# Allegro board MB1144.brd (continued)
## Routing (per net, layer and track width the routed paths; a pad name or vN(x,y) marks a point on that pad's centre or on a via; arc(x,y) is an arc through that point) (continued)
LCDSEG3: length 39.4
  TOP w0.127: v1(86.2,113.67) 86.33,113.54 88.11,113.54 88.61,114.05 88.61,115.19 89.88,116.46 89.88,120.65 89.63,120.9 81.5,120.9 R68.1
  BOTTOM w0.127: CN11.41 83.82,95.92 85.06,97.16 85.06,101.09 86.84,102.87 86.84,112.9 86.2,113.54 v1(86.2,113.67)
LCDSEG4: length 52.8
  TOP w0.127: v1(93.44,96.9) 82.3,96.9 CN11.39 ; v1(89.68,114.83) 89.71,114.86 89.71,115.14 90.65,116.08 90.65,121.16 88.87,122.94 81.5,122.94 80.74,123.7 R66.1
  BOTTOM w0.127: v1(93.44,96.9) 93.95,97.41 93.95,110.36 92.81,111.51 92.81,113.16 92.04,113.92 92.04,115.19 91.79,115.44 90.29,115.44 v1(89.68,114.83)
LCDSEG5: length 56.7
  TOP w0.127: v1(92.81,97.41) 92.68,97.28 81.38,97.28 79.98,95.89 CN11.37 ; 80.36,127.51 81.12,127.51 81.5,127.89 84.42,127.89 85.06,127.25 88.87,127.25 92.68,123.44 92.68,114.81 91.92,114.05 v1(91.92,113.41)
  BOTTOM w0.127: v1(92.81,97.41) 92.96,97.41 93.69,98.15 93.69,110.11 92.55,111.25 92.55,113.03 92.17,113.41 v1(91.92,113.41)
LCDSEG6: length 65.9
  TOP w0.127: v1(88.87,135.38) 88.36,135.38 84.6,131.62 84.6,130.61 84.17,130.18 81.88,130.18 80.61,128.91 R56.1
  BOTTOM w0.127: v1(88.87,135.38) 94.15,135.38 94.84,134.7 98.7,134.7 99.92,133.48 99.92,111.63 96.74,108.46 96.67,108.46 96.03,107.82 96.03,98.81 93.11,95.89 CN11.47
LCDSEG7: length 193.2
  TOP w0.127: v1(72.36,48.9) 72.36,48.77 72.49,48.64 72.49,48.23 U24.6 ; v1(112.97,87.35) 112.74,87.12 RS1.9 ; v1(35.91,90.81) 36.8,91.69 48.86,91.69 49.5,92.33 54.71,92.33 55.59,93.22 60.29,93.22 v1(60.42,93.34) 60.8,93.73 64.36,93.73 65.3,94.67 67.61,94.67 67.79,94.49 69.82,94.49 70.07,94.23 86.07,94.23 87.73,95.89 CN11.45 89.02,95.89 90.19,94.72 94.53,94.72 94.89,95.07 107.99,95.07 v1(108.25,94.82) ; v1(43.28,112.14) 42.77,112.65 42.77,120.14 44.04,121.41 44.04,123.06 45.56,124.59 48.1,124.59 48.36,124.84 50.77,124.84 51.07,125.15 U7.133
  BOTTOM w0.127: v1(35.91,90.81) 35.91,92.08 34.44,93.55 34.44,104.55 42.03,112.14 v1(43.28,112.14) ; v1(72.36,48.9) 69.89,48.9 69.06,49.73 67.76,49.73 67.13,49.1 67.13,47.21 66.85,46.93 66.07,46.93 65.82,47.19 65.82,50.48 65.25,51.05 65.25,58.88 64.56,59.56 64.56,65.53 62.33,67.77 62.33,74.6 59.53,77.39 59.53,92.46 v1(60.42,93.34) ; v1(108.25,94.82) 108.93,94.13 108.93,90.88 112.5,87.31 112.93,87.31 v1(112.97,87.35)
LCDSEG8: length 243.3
  TOP w0.127: U23.19 65.62,47.85 65.97,48.19 v1(66.66,48.19) ; v1(35.91,87.5) 38.45,87.5 42.26,83.69 44.67,83.69 46.81,85.83 50.54,85.83 50.95,86.23 52.65,86.23 v1(53.18,86.77) ; v1(112.97,85.72) 112.92,85.72 112.57,86.08 112.02,86.08 112,86.11 RS1.5 ; v1(43.28,112.9) 43.02,113.16 43.02,119.89 44.29,121.16 44.29,122.81 45.69,124.21 48.1,124.21 48.36,124.46 50.9,124.46 51.08,124.65 U7.134 ; v1(53.31,92.84) 54.32,92.84 54.96,93.47 59.91,93.47 60.42,93.98 64.23,93.98 65.25,95 67.66,95 67.91,94.74 70.07,94.74 70.33,94.49 85.69,94.49 86.36,95.15 CN11.43 ; v1(102.69,89.08) 108.45,89.08 v1(108.71,88.82)
  BOTTOM w0.127: v1(102.69,89.08) 102.13,89.08 99.28,86.23 85.82,86.23 84.55,87.5 84.55,93.22 86.36,95.03 CN11.43 ; v1(53.31,92.84) 53.31,90.3 52.57,89.56 52.57,87.43 53.18,86.82 v1(53.18,86.77) ; v1(35.91,87.5) 35.4,88.01 35.4,92.2 34.18,93.42 34.18,104.67 42.41,112.9 v1(43.28,112.9) ; v1(108.71,88.82) 108.68,88.8 108.68,87.66 109.16,87.17 111.07,87.17 112.31,85.93 112.77,85.93 v1(112.97,85.72) 115.54,83.16 115.54,78.87 115.34,78.66 115.34,78.31 115.54,78.11 115.54,72.8 111.22,68.48 111.22,59.56 110.97,59.31 110.97,50.42 109.16,48.62 96.44,48.62 95.65,49.4 79.6,49.4 78.96,50.04 72.1,50.04 71.76,50.38 67.64,50.38 66.54,49.27 66.54,48.31 v1(66.66,48.19)
LCDSEG9: length 65.2
  TOP w0.127: v1(28.3,94.16) 28.37,94.23 46.61,94.23 CN11.13 ; v1(50.01,123.44) 50.26,123.44 50.96,124.15 U7.135
  BOTTOM w0.127: v1(50.01,123.44) 49.5,122.94 46.45,122.94 42.89,119.38 40.35,119.38 29.28,108.3 29.28,100.57 28.52,99.81 28.52,94.39 v1(28.3,94.16)
LCDSEG10: length 126.7
  TOP w0.127: R50.1 80.74,135.64 81.76,134.62 84.68,134.62 88.61,138.56 v1(88.87,138.56) ; v1(62.73,101.75) 62.73,101.7 61.69,100.66 58.39,100.66 57.58,101.47 48.84,101.47 46.68,99.31 46.68,96.85 45.72,95.89 CN11.11 ; v1(65.75,94.13) 65.91,93.98 86.46,93.98 86.71,94.23 93.72,94.23 v1(93.92,94.03)
  BOTTOM w0.127: v1(93.92,94.03) 96.69,96.8 96.69,107.26 100.43,111 100.43,134.9 98.04,137.29 94.08,137.29 92.17,139.19 89.5,139.19 v1(88.87,138.56) ; v1(65.75,94.13) 64.92,94.97 64.92,99.01 62.73,101.19 v1(62.73,101.75)
LCDSEG11: length 205.8
  TOP w0.127: v1(110.08,137.92) 109.76,138.24 109.38,138.24 109.32,138.3 104.24,138.3 102.71,139.83 101.31,139.83 100.93,140.21 88.49,140.21 84.68,136.4 81.76,136.4 80.99,137.16 R48.1 ; v1(47.21,62.99) 47.36,63.14 48.79,63.14 51.73,60.2 60.01,60.2 61.28,61.47 67.2,61.47 71.52,65.79 86.46,65.79 v1(87.34,64.9)
  BOTTOM w0.127: v1(47.21,62.99) 47.21,69.47 44.06,72.62 44.06,93.75 43.18,94.63 CN11.9 ; v1(87.34,64.9) 103.73,64.9 108.12,69.29 108.12,79.27 106.95,80.44 106.95,93.65 107.61,94.31 107.61,95.33 108.6,96.32 108.6,110.06 107.03,111.63 107.03,111.96 107.05,111.99 107.05,114.99 107.26,115.19 107.26,115.21 108.05,116 108.05,126.62 108.3,126.87 108.3,136.32 109.9,137.92 v1(110.08,137.92)
LCDSEG12: length 176.4
  TOP w0.127: R39.2 v1(71.85,145.67) ; v1(22.98,133.93) 22.98,134.04 23.97,135.03 23.97,137.67 25.88,139.57 v1(29.94,139.57) ; v1(52.14,71.53) 51.96,71.35 51.12,71.35 50.9,71.12 32.1,71.12 v1(31.77,70.79)
  BOTTOM w0.127: v1(52.14,71.53) 52.14,71.78 55.01,74.65 55.01,85.8 54.71,86.11 54.71,92.33 55.88,93.5 CN11.19 ; v1(31.77,70.79) 31.77,71.2 28.31,74.65 28.31,75.59 28.11,75.79 28.11,88.44 23.34,93.21 23.34,95.96 21.48,97.82 21.48,100.75 23.98,103.25 23.98,111.12 23.62,111.48 23.62,113.18 24.48,114.05 24.48,124.43 24.86,124.82 24.86,126.62 22.52,128.96 22.52,133.48 v1(22.98,133.93) ; v1(29.94,139.57) 50.51,139.57 52.29,141.35 55.9,141.35 57.8,139.45 60.17,139.45 62.45,141.73 70.2,141.73 71.85,143.38 v1(71.85,145.67)
LCDSEG13: length 158
  TOP w0.127: R38.1 v1(69.31,145.67) ; v1(52.29,86.74) 52.17,86.61 50.95,86.61 50.41,86.08 46.65,86.08 44.52,83.95 42.39,83.95 38.32,88.01 33.12,88.01 30.19,85.09 v1(22.32,85.09) ; v1(32.61,140.08) 25.37,140.08 23.46,138.18 23.46,135.08 22.37,133.99 22.37,116.51 21.18,115.32 21.18,111.38 v1(21.3,111.25)
  BOTTOM w0.127: v1(52.29,86.74) 52.29,87 52.19,87.1 52.19,89.81 52.8,90.42 52.8,93.09 53.34,93.63 CN11.17 ; v1(22.32,85.09) 21.56,85.85 21.56,88.17 17.57,92.15 17.57,102.23 16.48,103.33 16.48,104.78 17.57,105.87 17.57,107.67 21.15,111.25 v1(21.3,111.25) ; v1(69.31,145.67) 69.44,145.67 71.09,144.02 71.09,143 70.07,141.99 62.2,141.99 60.04,139.83 57.8,139.83 55.9,141.73 51.91,141.73 50.26,140.08 v1(32.61,140.08)
LCDSEG14: length 56.7
  TOP w0.127: v1(57.63,100.46) 57.07,99.9 57.07,97.66 56.74,97.33 55.21,97.33 54.78,96.9 51.82,96.9 CN11.15 ; v1(65.88,125.48) 65.88,129.16 71.25,134.53 U7.75
  BOTTOM w0.127: v1(65.88,125.48) 65.88,125.6 65.63,125.86 63.82,125.86 59.79,121.82 59.79,115.32 59.28,114.81 59.28,114.17 59.79,113.67 59.79,110.87 58.97,110.06 58.97,102.69 57.63,101.35 v1(57.63,100.46)
LCDSEG15: length 49.9
  TOP w0.127: U7.76 70.75,134.53 65.37,129.16 65.37,125.09 v1(65.88,124.59)
  BOTTOM w0.127: v1(65.88,124.59) 65.88,124.08 64.36,122.56 63.19,122.56 61.94,121.31 61.94,109.98 60.75,108.79 60.75,100.76 62.58,98.93 62.58,96.52 63.21,95.89 CN11.25
LCDSEG16: length 51.4
  TOP w0.127: v1(48.23,93.22) 48.61,93.6 51.28,93.6 52.04,94.36 53.82,94.36 54.2,94.74 59.07,94.74 60.22,95.89 CN11.23 ; U7.139 50.23,122.15 49.5,121.41 45.69,121.41 44.55,120.27 44.55,111.07 v1(44.44,110.97)
  BOTTOM w0.127: v1(48.23,93.22) 47.36,94.08 47.36,106.33 44.44,109.25 v1(44.44,110.97)
LCDSEG17: length 213.9
  TOP w0.127: U7.110 55.85,136.65 57.42,135.08 57.42,132.05 56.22,130.84 56.22,126.35 v1(56.16,126.3) ; v1(64.93,48.51) 64.93,48.45 64.48,48.01 64.48,47.5 64.62,47.36 U23.17 ; v1(31.69,92.86) 32.05,93.22 47.21,93.22 48.1,94.11 51.02,94.11 51.78,94.87 53.56,94.87 54.45,95.76 54.45,95.89 55.47,96.9 57.4,96.9 CN11.21 ; v1(107.79,93.85) 107.54,94.11 105.78,94.11 105.38,94.51 96.64,94.51 94.84,92.71 64.33,92.71 62.76,91.14 62.76,89.84 62.2,89.28 56.36,89.28 56.1,89.53 v1(56.1,89.66) ; v1(113.61,87.3) 113.61,87.33 112.9,86.61 112,86.61 RS1.7
  BOTTOM w0.127: v1(64.93,48.51) 64.81,48.63 64.81,58.72 63.6,59.94 63.6,65.66 61.97,67.28 61.97,72.11 57.37,76.71 57.37,85.34 56.86,85.85 56.86,88.9 v1(56.1,89.66) 56.1,91.19 57.5,92.58 57.5,94.96 CN11.21 ; v1(56.16,126.3) 56.16,125.85 54.85,124.54 54.85,124.41 51.72,121.27 50.48,121.27 50.02,120.81 47.06,120.81 43.85,117.6 41.09,117.6 40.68,117.19 40.68,117.09 31.2,107.62 31.2,99.8 30.73,99.33 30.73,94.22 31.69,93.25 v1(31.69,92.86) ; v1(107.79,93.85) 108.68,92.96 108.68,90.75 112.59,86.84 113.13,86.84 113.61,87.33 v1(113.61,87.3)
LCDSEG18: length 26.2
  TOP w0.127: v1(70.07,108.03) 70.07,108.33 70.71,108.97 R97.1
  BOTTOM w0.127: v1(70.07,108.03) 70.07,108.33 69.56,108.84 64.23,108.84 62.6,107.21 62.6,104.55 67.2,99.95 69.44,99.95 70.03,99.36 70.03,96.98 CN11.31
LCDSEG19: length 26.1
  TOP w0.127: v1(70.71,107.95) 71.22,107.95 R98.1
  BOTTOM w0.127: CN11.29 67.13,97.34 67.13,99.59 62.3,104.42 62.3,107.44 64.08,109.22 69.95,109.22 70.71,108.46 v1(70.71,107.95)
LCDSEG20: length 27.7
  TOP w0.127: R99.1 73.76,108.58 72.99,107.82 v1(71.85,107.82)
  BOTTOM w0.127: CN11.27 65.81,95.89 65.17,96.52 65.17,99.85 65.12,99.9 65.12,101.21 62.02,104.3 62.02,107.7 63.93,109.6 70.2,109.6 71.34,108.46 71.34,108.2 71.72,107.82 v1(71.85,107.82)
LCDSEG21: length 56.9
  TOP w0.127: U7.137 51.74,123.15 51.53,122.94 49.88,122.94 49.37,123.44 49.37,123.7 49.12,123.95 46.07,123.95 44.67,122.56 44.67,121.03 43.94,120.29 43.94,107.65 v1(44.06,107.52)
  BOTTOM w0.127: v1(44.06,107.52) 44.49,107.09 44.49,105.05 43.48,104.04 43.48,101.88 42.31,100.71 42.31,94.97 43.78,93.5 43.78,82.96 42.11,81.28 42.11,79.17 43.17,78.11 CN14.9
LCDSEG22: length 92.8
  TOP w0.127: v1(90.9,114.55) 90.9,115.19 91.66,115.95 91.66,120.52 91.64,120.55 91.64,121.79 88.46,124.97 84.13,124.97 83.81,125.28 ; CN14.11 46.07,78.11 47.24,79.27 49.07,79.27 49.68,79.88 49.68,81.38 50.77,82.47 50.77,84.84 51.4,85.47 61.56,85.47 62.4,84.63 70.1,84.63 70.96,85.5 83.05,85.5 83.76,86.21 83.76,89.56 85.52,91.31 v1(85.95,91.31)
  BOTTOM w0.127: v1(85.95,91.31) 85.95,91.72 87.98,93.75 87.98,101.3 89.78,103.1 89.78,103.78 89.81,103.81 89.81,113.59 90.77,114.55 v1(90.9,114.55)
LCDSEG23: length 97.7
  TOP w0.127: CN14.13 49.93,79.78 49.93,81.18 51.02,82.27 51.02,84.71 51.53,85.22 61.41,85.22 62.27,84.35 70.2,84.35 71.09,85.24 83.18,85.24 84.02,86.08 84.02,89.43 85.13,90.55 85.82,90.55 v1(86.71,91.44) ; 80.36,125.35 80.74,125.35 81.76,126.36 84.42,126.36 84.68,126.62 87.98,126.62 92.17,122.43 92.17,115.06 91.03,113.92 v1(90.9,113.92)
  BOTTOM w0.127: v1(90.9,113.92) 90.9,111.51 92.55,109.86 92.55,104.62 90.01,102.08 90.01,95.33 86.71,92.02 v1(86.71,91.44)
LCDSEG24: length 101.8
  TOP w0.127: v1(42.54,103.07) 42.44,103.07 42.06,103.45 42.06,105.74 40.61,107.19 40.61,109.09 40.86,109.35 40.86,117.86 37.56,121.16 37.56,128.91 45.31,136.65 45.31,146.81 46.96,148.46 56.48,148.46 59.4,145.54 R36.1 ; v1(42.69,76.23) 42.92,76.45 49.14,76.45 50.79,78.11 CN14.15
  BOTTOM w0.127: v1(42.54,103.07) 42.49,103.07 42.06,102.64 42.06,94.64 41.83,94.41 41.83,78.03 42.72,77.14 42.72,76.25 v1(42.69,76.23)
LCDSEG25: length 104.8
  TOP w0.127: R33.1 58.01,146.07 56,148.08 47.21,148.08 45.69,146.56 45.69,136.4 37.94,128.65 37.94,121.16 41.12,117.98 41.12,109.22 40.86,108.97 40.86,107.44 42.61,105.69 v1(42.61,103.81) ; v1(41.37,76.2) 41.88,76.71 49.02,76.71 49.93,77.62 49.93,78.54 50.51,79.12 52.32,79.12 CN14.17
  BOTTOM w0.127: v1(42.61,103.81) 41.8,103 41.8,94.84 41.57,94.61 41.57,76.4 v1(41.37,76.2)
LCDSEG26: length 112.3
  TOP w0.127: v1(57.63,126.49) 57.63,130.66 59.75,132.79 U7.98 59.75,140.24 59.4,140.59 v1(59.4,140.84) ; CN14.19 54.78,78.11 53.64,76.96 50.13,76.96 49.37,76.2 44.16,76.2 43.66,75.69 33.75,75.69 v1(33.5,75.44)
  BOTTOM w0.127: v1(57.63,126.49) 57.4,126.49 56.73,125.83 56.51,125.83 55.11,124.43 55.11,124.3 51.82,121.02 50.58,121.02 50.12,120.56 47.17,120.56 43.75,117.14 41.09,117.14 31.46,107.51 31.46,99.7 30.98,99.22 30.98,94.41 33.88,91.52 33.88,75.82 v1(33.5,75.44) ; 58.16,144.38 58.16,143.64 58.67,143.13 60.04,143.13 60.29,142.88 60.29,141.45 59.68,140.84 v1(59.4,140.84)
LCDSEG27: length 115.2
  TOP w0.127: CN14.21 56.92,76.61 54.58,76.61 54.17,76.2 50.57,76.2 49.8,75.44 44.55,75.44 44.04,74.93 35.27,74.93 v1(34.51,74.17) ; v1(58.01,141.1) 58.01,140.69 58.39,140.31 58.82,140.31 59.25,139.88 U7.99 59.25,132.65 57.12,130.52 57.12,126.36 v1(57.63,125.86)
  BOTTOM w0.127: v1(58.01,141.1) 57.75,141.1 56.26,142.59 56.26,144.38 ; v1(57.63,125.86) 57.35,125.58 56.61,125.58 55.36,124.33 55.36,124.15 51.98,120.76 50.69,120.76 50.23,120.3 47.27,120.3 43.78,116.81 41.12,116.81 31.79,107.49 31.79,99.67 31.24,99.12 31.24,94.59 34.13,91.69 34.13,74.55 v1(34.51,74.17)
LCDSEG28: length 68.8
  TOP w0.127: U7.77 70.25,134.54 64.87,129.16 v1(64.87,125.35)
  BOTTOM w0.127: CN14.23 60.93,78.11 59.91,79.12 59.91,81.15 61.18,82.42 61.18,93.22 59.28,95.12 59.28,99.19 59.23,99.24 59.23,109.8 60.04,110.62 60.04,113.79 59.53,114.3 59.53,114.68 60.04,115.19 60.04,121.69 63.95,125.6 64.61,125.6 v1(64.87,125.35)
LCDSEG29: length 68.7
  TOP w0.127: U7.78 69.75,135.06 64.36,129.67 64.36,125.22 v1(64.87,124.71)
  BOTTOM w0.127: v1(64.87,124.71) 64.36,125.22 63.95,125.22 60.67,121.95 60.67,110.74 59.48,109.55 59.48,99.36 59.53,99.31 59.53,95.25 61.69,93.09 61.69,81.53 62.45,80.77 62.45,79.15 CN14.25
LCDSEG30: length 68.1
  TOP w0.127: U7.79 69.25,135.2 63.98,129.92 63.98,124.97 v1(64.23,124.71)
  BOTTOM w0.127: v1(64.23,124.71) 63.82,124.71 60.93,121.82 60.93,110.62 59.73,109.42 59.73,99.49 59.79,99.44 59.79,95.38 62.07,93.09 62.07,83.44 64.61,80.9 64.61,79.54 CN14.27
LCDSEG31: length 70.6
  TOP w0.127: U7.80 68.75,135.08 63.72,130.05 63.72,124.59 64.1,124.21 64.61,124.21 v1(64.87,123.95)
  BOTTOM w0.127: CN14.29 67.02,79.66 67.02,86.49 63.85,89.66 63.85,91.69 60.04,95.5 60.04,99.57 59.99,99.62 59.99,109.3 61.18,110.49 61.18,121.69 63.7,124.21 64.61,124.21 v1(64.87,123.95)
LCDSEG32: length 69.9
  TOP w0.127: v1(64.1,123.7) 64.1,123.83 63.34,124.59 63.34,130.3 68.25,135.21 U7.81
  BOTTOM w0.127: v1(64.1,123.7) 63.57,123.7 61.44,121.56 61.44,110.36 60.24,109.17 60.24,100.51 61.82,98.93 61.82,95.76 65.25,92.33 65.25,88.9 69.98,84.17 69.98,79.25 CN14.31
LCDSEG33: length 70.9
  TOP w0.127: U7.82 67.75,135.6 63.09,130.94 63.09,124.08 v1(64.1,123.06)
  BOTTOM w0.127: CN14.33 72.26,79.5 72.26,82.39 65.5,89.15 65.5,92.58 62.12,95.96 62.12,99.01 60.5,100.63 60.5,109.04 61.69,110.24 61.69,121.44 63.32,123.06 v1(64.1,123.06)
LCDSEG34: length 129.8
  TOP w0.127: v1(58.64,126.49) 58.52,126.62 58.52,130.68 60.67,132.84 63.34,132.84 66.52,136.02 66.52,138.05 66.25,138.31 U7.85 ; CN14.35 75.21,77.11 58.16,77.11 57.4,76.35 54.71,76.35 54.3,75.95 50.69,75.95 49.93,75.18 44.8,75.18 44.29,74.68 36.16,74.68 v1(35.91,74.42)
  BOTTOM w0.127: v1(58.64,126.49) 59.02,126.11 59.02,125.6 58.41,124.99 56.75,124.99 55.87,124.12 55.87,123.94 51.06,119.13 46.83,119.13 43.78,116.08 41.14,116.08 32.3,107.24 32.3,99.46 31.74,98.9 31.74,94.97 34.64,92.08 34.64,75.69 v1(35.91,74.42)
LCDSEG35: length 133.5
  TOP w0.127: v1(58.52,125.86) 58.13,126.24 58.13,130.81 60.42,133.1 63.21,133.1 66.26,136.14 66.26,137.92 65.75,138.43 U7.86 ; CN14.37 77.5,76.86 58.97,76.86 58.21,76.1 54.83,76.1 54.43,75.69 50.82,75.69 50.06,74.93 44.93,74.93 44.42,74.42 36.67,74.42 v1(35.91,73.66)
  BOTTOM w0.127: v1(58.52,125.86) 58.52,125.6 58.24,125.32 56.72,125.32 55.62,124.22 55.62,124.04 51.06,119.49 46.83,119.49 43.67,116.33 41.02,116.33 32.05,107.36 32.05,99.57 31.49,99.01 31.49,94.74 34.39,91.85 34.39,75.18 v1(35.91,73.66)
LCDSEG36: length 93.4
  TOP w0.127: v1(44.95,106.55) 45.31,106.91 45.31,120.14 46.07,120.9 50.01,120.9 50.25,121.15 U7.141 ; CN14.39 79.76,76.58 59.1,76.58 58.36,75.84 54.96,75.84 54.55,75.44 50.95,75.44 50.18,74.68 45.18,74.68 44.98,74.47 v1(44.98,73.89)
  BOTTOM w0.127: v1(44.98,73.89) 44.34,74.52 44.34,94.21 44.04,94.51 44.04,104.01 44.95,104.93 v1(44.95,106.55)
LCDSEG37: length 93.5
  TOP w0.127: U7.142 51.41,120.65 51.28,120.78 50.39,120.78 50.26,120.65 46.32,120.65 45.69,120.02 45.69,106.07 v1(46.58,105.18) ; v1(47.82,73.56) 48.69,74.42 50.39,74.42 51.15,75.18 54.68,75.18 55.09,75.59 58.54,75.59 59.28,76.33 82.04,76.33 CN14.41
  BOTTOM w0.127: v1(46.58,105.18) 46.86,104.9 46.86,87.63 48.48,86 48.48,82.55 47.39,81.46 47.39,73.99 v1(47.82,73.56)
LCDSEG38: length 73.8
  TOP w0.127: CN14.43 84.33,76.07 59.66,76.07 58.9,75.31 55.19,75.31 54.81,74.93 51.61,74.93 v1(51.05,74.37) ; v1(51.28,107.7) 51.15,107.82 R103.2
  BOTTOM w0.127: v1(51.28,107.7) 52.22,106.76 52.22,94.18 50.13,92.1 50.13,85.09 52.19,83.03 52.19,76.48 51.07,75.36 51.07,74.4 v1(51.05,74.37)
LCDSEG39: length 75.2
  TOP w0.127: CN14.45 86.61,75.82 60.04,75.82 59.28,75.06 55.31,75.06 54.93,74.68 52.01,74.68 v1(51.71,74.37) ; R104.2 v1(52.67,107.82)
  BOTTOM w0.127: v1(51.71,74.37) 51.71,75.49 52.44,76.23 52.44,83.16 50.39,85.22 50.39,91.8 52.47,93.88 52.47,100.79 52.67,100.99 v1(52.67,107.82)
LED_STLINK: length 77.9
  TOP w0.127: R253.1 R254.1 20.16,10.79 22.19,12.83 32.23,12.83 34.13,14.73 34.13,15.88 40.35,22.1 40.35,27.3 41.37,28.32 50.01,28.32 53.18,31.5 53.18,37.85 58.57,43.23 v1(59.1,43.23) ; U23.30 65.55,50.3 v1(65.36,50.1)
  BOTTOM w0.127: v1(65.36,50.1) 65.36,49.97 65.43,49.9 65.43,47.43 65.04,47.04 62.38,47.04 59.02,43.69 59.02,43.38 59.1,43.31 v1(59.1,43.23)
MICROAB_N: length 4.3
  TOP w0.155: R3.1 29.31,165.99 29.44,165.85 D1.D1 29.63,165.91 29.63,167.44 29.49,167.58 CN1.2
MICROAB_P: length 5.5
  TOP w0.155: CN1.3 30.14,167.46 30.01,167.33 30.01,165.91 D1.C1 30.07,165.87 30.45,166.24 31.21,166.24 31.46,165.99 R4.1
NE3_1DELAY: length 13.9
  TOP w0.127: U21.3 53.89,65.33 54.1,65.53 55.09,65.53 v1(55.59,66.04) ; U21.38 58.01,71.11 58.01,70.18 58.1,70.09 v1(58.1,69.77)
  BOTTOM w0.127: 55.72,63.75 55.09,64.39 55.09,65.53 v1(55.59,66.04) 55.59,66.8 58.1,69.3 v1(58.1,69.77) 58.16,69.84 58.16,70.89
NE3_2DELAY: length 2.8
  TOP w0.127: U21.11 57.88,63.64 57.88,62.41 57.96,62.33 v1(57.96,62.26)
  BOTTOM w0.127: v1(57.96,62.26) 57.85,62.26 57.37,62.74 57.37,63.37
NETB2_2: length 13.9
  TOP w0.127: B2.2 B2.3 74.45,12.77 R245.1 R244.1
NETB3_1: length 14
  TOP w0.127: B3.1 82.01,7.3 82.01,10.67 R248.1 83.41,13.59 83.41,14.86 81.38,16.89 U33.3
NETB3_2: length 24.6
  TOP w0.127: B3.2 84.42,5.46 85.69,5.46 86.46,4.7 86.46,4.06 85.06,2.67 83.41,2.67 79.47,6.6 79.47,11.18 R246.2 80.38,13.57 U33.1
NETB3_3: length 18.6
  TOP w0.127: B3.3 84.37,3.43 83.79,3.43 80.61,6.6 80.61,10.92 R247.1 81.76,13.59 81.76,15.76 80.88,16.64 U33.2
NETB3_4: length 14.4
  TOP w0.127: B3.4 89.2,8.26 87.34,8.26 86.07,9.53 R249.1 84.8,14.1 84.8,14.99 83.79,16 82.9,16 81.88,17.02 U33.4
NETB3_5: length 3.5
  TOP w0.127: R251.2 89,10.03 B3.5
NETB3_6: length 10.9
  TOP w0.127: U33.5 82.38,17.16 83.15,16.38 85.82,16.38 86.96,15.24 86.96,13.59 R250.1 87.73,10.74 B3.6
NETBT1_1: length 50.6
  TOP w0.127: BT1.1 26.84,49.07 26.44,49.48 v1(26.44,49.53)
  BOTTOM w0.127: JP12.3 20.03,84.2 21.3,82.93 21.3,76.07 21.43,75.95 21.43,72.31 26.33,67.41 26.33,49.63 v1(26.44,49.53)
NETC1_2: length 220.3
  TOP w0.127: CN2.33 46.2,167.89 C1.2 44.67,167.89 42.64,167.89 41.5,166.75 41.5,137.41 34.89,130.81 34.89,119.51 37.53,116.87 37.53,107.8 37.1,107.37 37.1,103.8 40.28,100.62 45.27,100.62 v1(45.43,100.46) ; v1(49.37,66.29) 50.39,67.31 54.83,67.31 55.59,68.07 85.19,68.07 85.69,68.58 85.69,68.96 v1(85.57,69.09)
  BOTTOM w0.127: v1(85.57,69.09) 87.34,70.87 87.34,81.41 80.36,88.39 80.36,100.2 80.87,100.71 80.87,105.41 81.43,105.97 81.43,107.01 80.61,107.82 80.61,113.92 79.22,115.32 79.22,115.95 78.58,116.59 74.77,116.59 ; v1(49.37,66.29) 49.24,66.29 48.87,66.66 48.87,69.59 46.58,71.88 46.58,83.95 45.18,85.34 45.18,94.61 44.82,94.97 44.82,99.85 v1(45.43,100.46)
NETC2_2: length 219
  TOP w0.127: v1(84.8,69.09) 84.68,68.96 84.68,68.83 84.17,68.33 55.47,68.33 54.71,67.56 49.88,67.56 v1(49.37,67.06) ; CN2.34 52.8,165.86 C2.2 44.8,166.5 42.64,166.5 41.88,165.74 41.88,137.29 35.15,130.56 35.15,119.74 37.81,117.07 37.81,107.58 37.39,107.16 37.39,103.95 40.37,100.97 v1(45.82,100.97)
  BOTTOM w0.127: v1(45.82,100.97) 46.58,100.2 46.58,87 46.83,86.74 46.83,72.39 49.37,69.85 v1(49.37,67.06) ; v1(84.8,69.09) 85.31,68.58 85.95,68.58 87.73,70.36 87.73,81.53 81.63,87.63 81.63,92.33 82.14,92.84 82.14,98.93 81.5,99.57 81.5,105.56 81.88,105.94 81.88,107.06 80.87,108.08 80.87,114.3 79.72,115.44 79.72,116.08 77.95,117.85 74.59,117.85
NETC3_1: length 150.7
  TOP w0.127: v1(91.15,102.36) 91.03,102.49 85.92,102.49 84.52,103.89 74.24,103.89 72.41,102.06 64.03,102.06 63.21,102.87 62.45,102.87 61.66,102.08 60.9,102.08 60.55,102.44 46.2,102.44 45.61,101.85 39.97,101.85 37.69,104.14 37.69,107.04 38.07,107.43 38.07,117.35 35.4,120.02 35.4,130.3 42.26,137.16 42.26,162.56 43.02,163.32 44.04,163.32 44.04,164.34 R7.2 ; SB17.1 88.36,125.73 91.89,122.2 91.89,120.68 91.92,120.65 91.92,115.57 91.41,115.06 v1(91.41,114.94)
  BOTTOM w0.127: v1(91.15,102.36) 91.15,102.62 92.93,104.39 92.93,109.98 91.41,111.51 v1(91.41,114.94)
NETC4_2: length 136.2
  TOP w0.127: 43.78,160.78 C4.2 44.55,162.81 47.72,162.81 48.48,163.58 53.94,163.58 54.83,164.47 54.83,166.88 CN2.31 ; v1(82.21,104.5) 74.16,104.5 72.18,102.51 63.95,102.51 63.34,103.12 62.33,103.12 61.59,102.39 61,102.39 60.7,102.69 46.04,102.69 45.46,102.11 40.23,102.11 37.94,104.39 37.94,106.81 38.32,107.19 38.32,117.73 35.66,120.4 35.66,130.18 42.51,137.03 42.51,158.62 43.4,159.51 43.4,160.27 43.53,160.4
  BOTTOM w0.127: 81.12,115.44 81.12,108.2 82.39,106.93 82.39,104.67 v1(82.21,104.5)
NETC5_2: length 47.3
  TOP w0.127: R20.1 52.8,159.77 v1(53.18,160.15) 52.8,160.53 C5.2 54.07,162.18 54.71,162.18 57.88,165.35 CN2.30 ; v1(70.58,143.13) 70.71,143 71.47,143 72.1,142.37 SB3.1
  BOTTOM w0.127: v1(53.18,160.15) 53.44,159.89 53.44,144.58 57.93,140.08 59.79,140.08 62.07,142.37 69.69,142.37 70.45,143.13 v1(70.58,143.13)
NETC6_2: length 159.9
  TOP w0.127: v1(37.76,91.06) 38.14,91.44 49.12,91.44 49.63,91.95 54.71,91.95 55.59,92.84 60.93,92.84 61.56,93.47 86.84,93.47 v1(87.09,93.73) ; 87.09,122.05 87.1,122.06 89.37,122.06 90.39,121.03 90.39,116.2 89.22,115.04 89.22,114.6 v1(89.66,114.17) ; v1(38.5,106.27) 38.58,106.35 38.58,117.86 35.91,120.52 35.91,129.92 42.77,136.78 42.77,154.69 47.59,159.51 C6.2 R12.2
  BOTTOM w0.127: v1(87.09,93.73) 87.73,94.36 87.73,101.47 89.5,103.25 89.5,114.02 v1(89.66,114.17) ; v1(37.76,91.06) 37.43,91.39 37.43,94.23 37.23,94.44 37.23,105 v1(38.5,106.27)
NETC7_2: length 72.6
  TOP w0.127: CN2.1 95.09,166.75 95.09,160.27 C7.2 R14.1
  BOTTOM w0.127: CN2.1 91.66,170.18 78.45,170.18 77.24,168.96 77.24,164.95 75.99,163.7 57.25,163.7 55.85,162.31 55.85,159.99 56.81,159.03 56.81,147.93 56.24,147.35 56.24,145.36
NETC8_1: length 1.3
  TOP w0.127: SB1.1 46.45,160.53 C8.1
NETC9_2: length 112.2
  TOP w0.127: v1(61.28,102.87) 61.18,102.97 45.87,102.97 45.26,102.36 40.35,102.36 38.96,103.76 38.96,117.86 36.16,120.65 36.16,129.67 43.02,136.53 43.02,154.31 44.8,156.08 49.5,156.08 49.75,156.34 49.75,160.15 C9.2 50.64,161.04 50.64,161.42 51.78,162.56 54.58,162.56 57.12,165.1 57.12,166.62 CN2.29
  BOTTOM w0.127: 63.12,111.99 62.2,111.07 62.2,109.86 61,108.66 61,103.15 v1(61.28,102.87)
NETC10_2: length 174.9
  TOP w0.127: v1(79.72,105.41) 79.98,105.16 84.14,105.16 86.05,103.25 92.17,103.25 97.89,97.54 112.11,97.54 v1(112.29,97.36) ; R17.1 C10.2 59.1,160.22 59.1,161.11 59.79,161.8 v1(60.55,161.8)
  BOTTOM w0.127: v1(112.29,97.36) 112.31,97.36 113.96,99.01 113.96,114.71 113.66,115.01 113.66,127 115.11,128.45 115.11,135.23 117.21,137.34 117.21,140.23 117.19,140.26 117.19,140.67 117.21,140.69 117.21,143.1 117.93,143.81 117.93,153.06 115.64,155.35 108.65,155.35 106.94,157.06 106.94,162.9 103.85,165.99 98.39,165.99 96.62,164.21 83.41,164.21 81.95,162.75 80.3,162.75 79.34,161.8 v1(60.55,161.8) ; 77.9,112.26 77.9,110.11 78.71,109.3 78.71,106.43 v1(79.72,105.41)
NETC11_1: length 108.1
  TOP w0.127: 83.92,127.13 84.68,127.13 84.93,126.87 88.74,126.87 92.42,123.19 92.42,114.94 91.41,113.92 91.41,112.78 92.58,111.61 95.35,111.61 95.95,111 101.44,111 102.58,112.14 102.58,114.43 103.35,115.19 106.62,115.19 v1(106.8,115.37) ; v1(103.09,159.77) 97.12,159.77 96.23,158.88 88.36,158.88 R19.1 C11.1 R13.2
  BOTTOM w0.127: v1(106.8,115.37) 107.66,116.23 107.66,125.86 107.79,125.98 107.79,126.75 108.05,127 108.05,136.53 110.28,138.76 110.28,150.44 109.14,151.59 107.64,151.59 103.09,156.14 v1(103.09,159.77)
NETC13_2: length 150.3
  TOP w0.127: C13.2 R10.1 80.61,161.29 v1(80.61,161.8) ; v1(112.13,98.3) 112.11,98.3 111.98,98.17 98.27,98.17 92.55,103.89 86.25,103.89 84.35,105.79 80.49,105.79 v1(79.85,106.43)
  BOTTOM w0.127: v1(112.13,98.3) 112.24,98.3 113.33,99.39 113.33,114.43 112.95,114.81 112.95,127.18 114.47,128.7 114.47,135.51 116.55,137.59 116.55,143.36 117.29,144.09 117.29,152.78 115.36,154.71 108.27,154.71 106.22,156.76 106.22,162.6 103.47,165.35 98.77,165.35 97,163.58 83.79,163.58 82.01,161.8 v1(80.61,161.8) ; v1(79.85,106.43) 79.34,106.93 79.34,112.65 SB36.1
NETC14_2: length 146.7
  TOP w0.127: C14.2 R11.1 83.28,161.67 v1(83.28,162.05) ; v1(80.87,106.43) 84.52,106.43 86.43,104.52 92.93,104.52 98.65,98.81 111.65,98.81 111.98,99.14 v1(112.06,99.14)
  BOTTOM w0.127: 77.9,115.56 77.95,115.56 79.98,113.53 79.98,107.31 v1(80.87,106.43) ; v1(112.06,99.14) 112.74,99.82 112.74,114.02 111.55,115.21 111.55,122.48 112.29,123.22 112.29,127.38 113.84,128.93 113.84,135.79 115.92,137.87 115.92,143.64 116.66,144.37 116.66,151.84 114.42,154.08 107.89,154.08 105.51,156.46 105.51,162.31 103.09,164.72 99.16,164.72 97.38,162.94 84.17,162.94 v1(83.28,162.05)
NETC15_1: length 131.9
  TOP w0.254: D1.B3 30.57,164.85 31.08,164.34 31.34,164.34 v1(31.46,164.47)
  TOP w0.381: CN1.1 28.84,167.56 28.29,167 v1(27.78,167)
  TOP w0.508: v1(27.78,167) R2.2 25.5,165.99 R1.1 ; v1(21.43,143.51) 27.53,149.61 27.53,156.34 25.88,157.99 v1(25.88,159.38) 25.5,159.77 C15.1 23.33,159.77 U1.1 ; R108.2 48.86,100.71 47.19,99.03 47.19,95.73 46.25,94.79 34.97,94.79 34.13,95.63 34.13,97.31 30.86,100.58 15.34,100.58 14.45,101.47 v1(14.45,113.41)
  BOTTOM w0.508: v1(21.43,143.51) 21.43,143.1 18.89,140.56 18.89,137.21 18.26,136.58 18.26,122.56 15.84,120.14 15.84,114.81 v1(14.45,113.41) ; v1(25.88,159.38) 25.88,162.69 26.89,163.7 26.89,166.12 v1(27.78,167) 28.92,167 v1(31.46,164.47)
NETC16_2: length 95.9
  TOP w0.127: SB25.2 63.37,108.71 61.56,106.91 61.56,104.67 60.12,103.23 45.69,103.23 45.08,102.62 40.61,102.62 39.34,103.89 39.34,117.86 36.42,120.78 36.42,129.54 43.28,136.4 43.28,153.67 45.31,155.7 51.02,155.7 C16.2 53.18,158.5 R15.1
NETC17_1: length 218.2
  TOP w0.127: R16.2 C17.1 55.47,156.34 54.32,155.19 45.46,155.19 43.53,153.27 43.53,136.27 36.67,129.41 36.67,120.9 39.59,117.98 39.59,105.03 v1(39.97,104.65) ; v1(84.04,118.36) 83.92,118.49 SB22.1 ; v1(41.88,68.96) 41.88,67.31 43.4,65.79 49.63,65.79 50.9,67.06 54.96,67.06 55.72,67.82 85.82,67.82 v1(87.09,69.09)
  BOTTOM w0.127: v1(39.97,104.65) 39.21,103.89 39.21,91.95 38.96,91.69 38.96,71.88 v1(41.88,68.96) ; v1(87.09,69.09) 92.81,74.8 92.81,85.09 92.23,85.66 85.76,85.66 84.17,87.25 84.17,94.36 85.44,95.63 85.44,101.09 87.22,102.87 87.22,113.54 83.66,117.09 83.66,117.98 v1(84.04,118.36)
NETC23_2: length 14
  TOP w0.254: C23.2 17.69,151.96 U4.2 ; C23.2 16.99,151.38 v1(16.35,150.75) ; C23.2 17.18,151.31 U4.3 ; U4.9 23.8,150.66 C28.1 22.96,149.73 v1(22.83,149.73)
  BOTTOM w0.254: v1(22.83,149.73) 17.37,149.73 v1(16.35,150.75)
NETC24_2: length 17
  TOP w0.254: C24.2 4.54,151.26 4.54,151.31 U3.3 ; C24.2 3.65,151.26 v1(3.02,150.62) ; C24.2 4.48,151.96 U3.2 ; U3.9 9.45,150.62 C27.1 v1(11.78,150.62)
  BOTTOM w0.254: v1(3.02,150.62) 4.21,149.43 10.59,149.43 v1(11.78,150.62)
NETC25_2: length 2.1
  TOP w0.127: C25.2 17.98,150.11 18.53,150.66 U4.4
NETC26_2: length 2.3
  TOP w0.127: U3.4 4.71,150.66 4.03,149.99 C26.2
NETC29_1: length 12.8
  TOP w0.127: U3.5 6.49,148.88 v1(6.45,148.84) 6.06,148.84 C29.1 ; CN4.2 7.08,145.67 R26.2 7.33,147.19 R27.1 8.44,148.3 U3.8
  BOTTOM w0.127: v1(6.45,148.84) 6.32,148.72 6.32,144.91 CN4.2
NETC30_1: length 7
  TOP w0.102: 96.87,147.05 97.25,146.67 99.07,146.67 99.45,147.05 U5.B5
  TOP w0.127: 96.87,147.05 96.86,147.07 C30.1 R28.2
NETC34_2: length 1.8
  TOP w0.127: C34.2 SB4.1
NETC37_2: length 2.2
  TOP w0.127: 68.85,142.1 68.85,144.25 C37.2
NETC47_2: length 7.8
  TOP w0.127: R73.2 80.99,120.4 85.44,120.4 R72.1 C47.2
NETC52_2: length 14.6
  TOP w0.254: U7.32 70.25,115.9 70.33,115.82
  TOP w0.508: R92.2 80.36,111.12 79.72,111.76 79.72,112.39 79.09,113.03 C52.2 77.82,113.03 C53.1 76.3,114.55 71.47,114.55 70.33,115.7 70.33,115.82
NETC55_1: length 6.7
  TOP w0.203: 66.26,109.86 67.28,108.84 R95.2 67.41,107.95 69.69,105.66 X2.1
NETC56_1: length 6.8
  TOP w0.127: R87.1 58.01,110.49 C56.1 57.02,109.63 57.02,107.47 X1.2
NETC57_1: length 6.8
  TOP w0.127: R88.1 59.15,111.63 C57.1 59.79,109.6 59.79,107.94 X1.1
NETC62_1: length 2
  TOP w0.127: C62.1 102.86,102.77 U10.24
NETC62_2: length 3.2
  TOP w0.127: U10.28 103.63,100.17 103.37,100.43 103.37,101.32 102.71,101.98
NETC63_1: length 1.9
  TOP w0.127: U10.3 113.25,101.47 C63.1
NETC64_1: length 2
  TOP w0.127: U10.1 112.91,100.17 C64.1
NETC64_2: length 1.9
  TOP w0.127: C64.2 113.27,100.82 U10.2
NETC65_1: length 5.2
  TOP w0.127: C65.1 105.38,99.44 105.76,99.82 105.76,100.53 105.47,100.82 U10.27
NETC67_1: length 7.1
  TOP w0.254: C67.1 9.49,95.5 7.08,95.5 R115.2 C68.2 6.16,94.59 U11.6
NETC73_1: length 55.7
  TOP w0.127: R69.2 80.49,120.65 89.38,120.65 89.63,120.4 89.63,116.59 88.11,115.06 v1(88.11,114.68) ; R122.2 C73.1 72.84,91.69 73.17,92.02 85.01,92.02 v1(85.19,92.2)
  BOTTOM w0.127: v1(88.11,114.68) 88.11,114.43 89.25,113.28 89.25,103.5 87.47,101.73 87.47,95 85.19,92.71 v1(85.19,92.2)
NETC77_1: length 1.9
  TOP w0.127: U14.9 81.36,86.75 C77.1
NETC77_2: length 2.2
  TOP w0.127: R130.2 R134.2 C77.2
NETC80_1: length 15.3
  TOP w0.508: U20.3 22.26,71.31 22.73,71.78 22.73,72.64 22.16,73.21 U20.1 20.1,73.21 C80.1 19.27,73.15 18.91,73.51 D8.2 D7.2 D6.2 12.45,73.53 10.2,73.53 D5.2
NETC82_1: length 1.7
  TOP w0.127: U20.4 23.9,70.54 C82.1
NETC102_1: length 6.7
  TOP w0.089: U29.H8 78.7,33.03 78.7,33.53
  TOP w0.127: 78.7,33.53 78.7,33.67 76.08,36.28 76.08,37.68 C102.1
NETC102_2: length 5.7
  TOP w0.089: 78.2,33.53 78.48,33.24 78.48,32.89 78.73,32.64 U29.G8
  TOP w0.127: C102.2 75.41,36.32 78.2,33.53
NETC103_1: length 5.3
  TOP w0.089: U29.G7 79.23,32.5 78.98,32.74 78.98,33.52 78.98,33.53
  TOP w0.127: C103.1 76.8,36.2 78.98,34.02 78.98,33.53
NETC104_1: length 4.3
  TOP w0.089: U29.H7 79.23,33.53
  TOP w0.127: C104.1 78.07,35.43 79.23,34.27 79.23,33.53
NETC105_1: length 65.6
  TOP w0.089: 79.63,33.53 79.48,33.38 79.48,32.76 79.73,32.5 U29.G6
  TOP w0.127: 79.63,33.53 79.6,33.53
  TOP w0.203: 79.6,33.53 79.6,35.31 79.22,35.69 79.22,36.7 79.72,37.21 79.72,40.26 81.38,41.91 92.3,41.91 95.65,38.56 95.65,36.14 98.14,33.66 102.46,33.66 109.57,40.77 111.22,40.77 112.87,42.42 115.03,42.42 117.8,39.65 117.8,35.64 CN20.4
NETC105_2: length 1.1
  TOP w0.127: R195.1 C105.2
NETC106_1: length 48
  TOP w0.203: CN20.6 109.76,40.19 102.71,33.15 97.89,33.15 95.02,36.02 95.02,38.3 91.92,41.4 83.41,41.4 80.99,38.99 80.99,37.47 80.36,36.83 v1(80.36,35.94) 79.96,35.55 79.96,33.22 U29.H6
NETC106_2: length 1.1
  TOP w0.127: R196.1 C106.2
NETC108_1: length 7.2
  TOP w0.089: U29.E6 79.73,31.49 79.48,31.74 79.13,31.74 78.98,31.89 78.98,32.09 78.83,32.24 78.63,32.24 78.48,32.39 78.48,32.59 78.34,32.74 78.31,32.74 78.31,32.74 77.82,32.74
  TOP w0.127: C108.1 75.41,34.92 76.17,34.92 76.8,34.29 76.8,33.4 77.46,32.74 77.82,32.74
NETC110_1: length 4.1
  TOP w0.089: U29.F1 82.65,31.99
  TOP w0.127: 82.65,31.99 82.97,31.99 83.47,32.49 83.89,32.49 C110.1
NETC113_1: length 12.6
  TOP w0.508: L3.1 93.57,33.27 C115.2 95.35,33.91 C113.1 v1(97,33.15)
  BOTTOM w0.508: CN19.22 101.26,36.4 100.11,35.25 100.11,34.11 99.41,33.4 97.38,33.4 97.12,33.15 v1(97,33.15)
NETC114_1: length 7.8
  TOP w0.508: U26.1 30.31,36.54 ; U26.1 30.31,34.38 ; U26.1 29.62,35.46 ; U26.1 30.99,35.46 ; 27.83,33.15 R209.2 ; R209.2 29,33.15 ; R209.2 28.42,33.72 ; 31.34,33.48 R207.1 30.77,32.89 ; C114.1 29.81,33.48 ; C114.1 30.27,33.02 ; C114.1 29.36,33.02
NETC117_2: length 8.8
  TOP w0.127: 68.42,28.8 68.42,29.46 v1(69.37,30.42) 69.37,30.92 C117.2
  BOTTOM w0.127: v1(69.37,30.42) 72.8,30.42 73.63,29.59 CN23.1
NETC122_1: length 3.8
  TOP w0.089: U29.D9 77.82,30.99
  TOP w0.127: C122.1 75.79,29.84 76.93,30.99 77.82,30.99
NETC124_1: length 24.7
  TOP w0.508: C124.1 19.02,29.67 ; C124.1 19.48,29.21 ; C124.1 19.02,28.75 ; U31.3 18.9,25.62 ; U31.3 18.26,25.14 ; U31.3 18.26,26.1 ; 21.43,31.37 Z1.2 ; Z1.2 21.43,33.4 ; Z1.2 22.61,32.38 ; Z1.2 20.24,32.38
  TOP w1.143: 20.54,34.67 9.9,34.67 6.89,31.66 L2.1
NETC124_2: length 26
  TOP w0.508: U31.2 16.99,26.1 ; U31.2 16.34,25.62 ; U31.2 16.99,25.14 ; CN22.2 7.54,17.78 ; CN22.2 9.82,16.59 ; CN22.2 5.25,16.59 ; CN22.2 7.54,15.4 ; L2.2 9.49,32.83 ; L2.2 9.49,30.49 ; L2.2 8.32,31.66 ; L2.2 10.65,31.66 ; C124.2 18,29.67 ; C124.2 17.54,29.21 ; C124.2 18,28.75 ; 16.44,32.38 Z1.1 ; Z1.1 17.63,31.37 ; Z1.1 18.81,32.38 ; Z1.1 17.63,33.4 ; CN22.3 4.44,23.88 ; CN22.3 3.24,21.59 ; CN22.3 5.63,21.59 ; CN22.3 4.44,19.3
NETC125_2: length 5
  TOP w0.127: C125.2 75.53,27.69 75.53,28.14 77.87,30.48 78.22,30.48 U29.C9
NETC127_2: length 88.9
  TOP w0.127: U29.A7 79.22,29.48 79.22,28.83 v1(77.95,27.56) 77.95,26.8 C127.2
  BOTTOM w0.127: JP16.1 25.55,76.78 25.55,73.1 29.81,68.83 35.78,68.83 42.39,62.23 42.39,46.15 56.66,31.88 69.06,31.88 70.2,30.73 73.37,30.73 76.55,27.56 v1(77.95,27.56)
NETC128_2: length 4
  TOP w0.089: U29.B6 79.48,29.74 79.48,28.96
  TOP w0.127: C128.2 79.48,26.93 79.48,28.96
NETC129_1: length 2.7
  TOP w0.381: R227.2 C129.1 R226.2
NETC129_2: length 4.6
  TOP w0.229: U29.B3 81.23,29.99 80.98,29.74 v2(80.98,29.74)
  TOP w0.508: C129.2 v1(81.63,27.3)
  BOTTOM w0.381: v2(80.98,29.74) 81.26,29.74 82.01,28.99 82.01,27.69 v1(81.63,27.3)
NETC130_1: length 2.2
  TOP w0.203: R225.1 R224.2 C130.1
NETC130_2: length 5.9
  TOP w0.203: C130.2 84.8,25.53 81.88,28.45 81.88,29.36 81.76,29.49 U29.A2
NETC136_1: length 7.8
  TOP w0.127: C136.1 v1(58.26,16.13) ; U30.7 62.07,18.29 v1(62.58,17.78)
  BOTTOM w0.127: v1(58.26,16.13) 59.91,17.78 v1(62.58,17.78)
NETC136_2: length 2.1
  TOP w0.127: C136.2 59.53,17.27 U30.5
NETC137_1: length 2.1
  TOP w0.127: 63.34,19.21 63.34,17.27 C137.1
NETC139_1: length 171.5
  TOP w0.127: U36.1 11.8,13 12.44,13.64 13,13.64 C142.1 v1(14.62,12.95) ; U35.1 97.57,15.54 98.19,16.15 99,16.15 C139.1 99.54,15.88 99.54,16.99 99.26,17.27 R238.2 96.39,18.01 94.81,18.01 93.19,16.38 v1(93.19,15.16)
  BOTTOM w0.127: JP16.2 22.57,72.09 27.27,67.39 27.27,33.66 14.62,21.01 v1(14.62,12.95) 14.62,12.32 18.89,8.05 26.94,8.05 29.81,10.92 88.94,10.92 v1(93.19,15.16)
NETC144_1: length 5.6
  TOP w0.127: U15.3 42.89,89.3 42.64,89.55 42.64,90.3 42.39,90.55 C144.1 R124.1 R128.2
NETCN1_4: length 8.5
  TOP w0.127: v1(31.59,165.35) 31.09,164.85 D1.A3 ; CN1.4 30.79,167.17 31.08,166.88 33.12,166.88 R5.1 33.37,165.35 v1(33.24,165.35)
  BOTTOM w0.127: v1(33.24,165.35) v1(31.59,165.35)
NETCN2_3: length 56.9
  BOTTOM w0.127: CN2.3 90.01,169.29 88.36,169.29 87.47,168.4 87.47,167.13 87.09,166.75 82.77,166.75 82.39,166.37 82.39,164.97 81.5,164.08 80.23,164.08 78.84,162.69 57.88,162.69 57.12,161.93 57.12,160.81 58.01,159.92 58.01,147.27 58.87,146.41 58.87,145.95 SB27.1
NETCN2_5: length 112.1
  TOP w0.127: v1(105.68,166.9) 107.18,165.4 107.18,156.01 108.96,154.23 109.77,154.23 111.25,152.76 111.25,138.58 110.84,138.18 v1(110.71,138.18) ; v1(108.53,116.38) 108.48,116.38 107,114.91 103.91,114.91 103.12,114.12 103.12,112.17 101.7,110.74 94.71,110.74 94.58,110.62 92.81,110.62 90.14,113.28 90.14,115.19 90.9,115.95 90.9,121.41 89.12,123.19 84.17,123.19 SB19.1
  BOTTOM w0.127: CN2.5 89.86,166.9 v1(105.68,166.9) ; v1(108.53,116.38) 108.55,116.38 108.81,116.64 108.81,126.75 108.55,127 108.55,136.14 109.57,137.16 110.46,137.16 110.71,137.41 v1(110.71,138.18)
NETCN2_7: length 56.2
  BOTTOM w0.127: CN2.7 85.06,169.16 78.38,169.16 77.59,168.38 77.59,164.67 76.28,163.36 57.41,163.36 56.36,162.31 56.36,160.2 57.25,159.31 57.25,142.43 57.55,142.13
NETCN2_9: length 87
  TOP w0.127: CN2.9 85.03,169.14 98.7,169.14 102.97,164.87 102.97,162.33 v1(103.45,161.85) ; 87.34,128.14 88.74,128.14 90.52,129.92 90.52,132.59 91.54,133.6 91.54,136.91 92.55,137.92 98.9,137.92 99.41,137.41 101.7,137.41 103.35,135.76 108.81,135.76 v1(109.06,135.51)
  BOTTOM w0.127: v1(103.45,161.85) 103.65,161.65 103.65,156.21 106.45,153.42 106.46,153.42 107.73,152.15 109.83,152.15 111.07,150.91 111.07,139.25 111.27,139.05 111.27,137.4 110.77,136.91 110.2,136.91 109.06,135.76 v1(109.06,135.51)
NETCN2_11: length 45.4
  BOTTOM w0.127: SB28.1 57.63,145.8 57.63,159.61 56.74,160.5 56.74,162.18 57.63,163.07 78.45,163.07 80.11,164.72 80.11,166.75 CN2.11
NETCN2_13: length 95.5
  TOP w0.127: 84.05,129.42 84.18,129.42 84.93,130.18 88.61,130.18 89.12,130.68 89.12,133.73 90.94,135.55 90.94,136.87 92.25,138.18 99.16,138.18 99.66,137.67 101.82,137.67 103.47,136.02 109.44,136.02 v1(109.95,135.51) ; v1(103.55,163.04) 103.55,164.8 98.83,169.52 80.33,169.52 CN2.13
  BOTTOM w0.127: v1(109.95,135.51) 109.95,136.14 110.33,136.53 110.79,136.53 111.6,137.34 111.6,139.12 111.35,139.37 111.35,151.03 109.95,152.43 107.84,152.43 104.01,156.26 104.01,162.59 v1(103.55,163.04)
NETCN2_14: length 8.6
  TOP w0.127: CN2.14 79.98,164.08 82.52,164.08 R13.1
NETCN2_15: length 10.4
  TOP w0.127: R11.2 80.23,163.19 78.96,163.19 77.44,164.72 77.44,166.62 CN2.15
NETCN2_17: length 9.6
  TOP w0.127: CN2.17 75.03,166.5 75.03,164.97 78.45,161.54 78.84,161.54 R10.2
NETCN2_19: length 18.5
  TOP w0.127: CN2.19 70.07,166.88 70.07,165.16 67.72,162.81 58.13,162.81 56.86,161.54 R17.2
NETCN2_21: length 48.8
  TOP w0.127: v1(63.65,142.98) 63.83,142.79 63.83,142.14
  BOTTOM w0.127: v1(63.65,142.98) 63.57,143.05 62.38,143.05 59.66,140.34 58.06,140.34 54.96,143.43 54.96,147.07 56.38,148.49 56.38,158.83 55.34,159.87 55.34,162.56 56.86,164.08 66.77,164.08 67.23,164.54 67.23,166.57 CN2.21
NETCN2_23: length 103.7
  TOP w0.127: SB11.1 84.07,131.47 84.07,131.85 90.9,138.68 99.54,138.68 100.04,138.18 102.08,138.18 103.47,136.78 v1(107.03,136.78) ; v1(103.14,160.6) 104.08,161.54 104.08,164.85 99.03,169.9 68.01,169.9 CN2.23
  BOTTOM w0.127: v1(103.14,160.6) 102.58,160.05 102.58,156.29 103.45,155.42 103.45,154.46 103.96,153.95 103.96,153.03 105.18,151.82 106.82,151.82 107.31,151.33 109.01,151.33 110.03,150.32 110.03,139.9 107.92,137.79 107.92,137.41 107.28,136.78 v1(107.03,136.78)
NETCN2_24: length 26.9
  TOP w0.127: R7.1 45.82,164.08 53.69,164.08 54.45,164.85 54.45,168.28 55.21,169.04 61.31,169.04 61.94,168.4 61.94,167.64 62.83,166.75 64.61,166.75 CN2.24
NETCN2_26: length 9.8
  TOP w0.127: R16.1 58.26,163.7 61.82,163.7 CN2.26
NETCN2_27: length 10.9
  TOP w0.127: R15.2 55.34,162.18 55.34,162.31 57.14,164.11 59.02,164.11 59.63,164.72 59.63,166.6 CN2.27
NETCN2_32: length 8.9
  TOP w0.127: CN2.32 55.85,164.72 54.32,163.19 51.28,163.19 R12.1
NETCN3_4: length 161.8
  TOP w0.127: v1(86.2,20.57) 85.57,21.21 84.68,21.21 84.28,20.81 U33.12 ; CN3.4 v1(118.71,151.16) ; v1(118,64.21) 118,64.14 112.54,58.67 106.78,58.67 103.6,55.5 v1(103.6,42.16)
  BOTTOM w0.127: v1(86.2,20.57) 86.84,20.57 87.85,21.59 87.85,22.61 90.14,24.89 90.14,27.81 89.76,28.19 89.76,37.85 92.93,41.02 102.46,41.02 v1(103.6,42.16) ; v1(118.71,151.16) 118.89,150.98 118.89,129.84 115.03,125.98 115.03,94.64 118.99,90.68 118.99,71.37 118,70.38 v1(118,64.21)
NETCN3_8: length 3.7
  TOP w0.127: v1(113.63,150.44) CN3.8
  BOTTOM w0.127: SB43.1 v1(113.63,150.44)
NETCN4_1: length 7.4
  TOP w0.127: U3.6 7.14,148.26 R26.1 6.45,147.57 6.45,146.43 5.81,145.8 4.67,145.8 CN4.1
NETCN5_2: length 18.5
  TOP w0.127: CN5.2 11.53,126.49 13.81,126.49 14.66,127.34 D2.2 15.27,125.92 15.84,125.35 18.76,125.35 19.27,125.86 U8.6 19.27,132.08 JP6.2
NETCN5_5: length 4
  TOP w0.127: R77.2 12.49,119.56 CN5.5
NETCN5_7: length 19.8
  TOP w0.127: R55.1 U8.7 18,125.98 17.75,125.73 16.35,125.73 15.97,126.11 15.97,128.14 15.59,128.52 13.81,128.52 13.37,128.08 D2.1 12.08,127.34 11.78,127.64 11.78,128.4 11.02,129.16 9.49,129.16 7.37,127.03 CN5.7
NETCN5_9: length 6.8
  TOP w0.127: R70.2 12.62,120.95 CN5.9
NETCN6_2: length 5.4
  TOP w0.127: CN6.2 R44.2
NETCN6_30: length 6.3
  TOP w0.127: 36.93,116.46 35.15,116.46 32.73,118.87 CN6.30
NETCN7_24: length 50.2
  TOP w0.127: CN7.24 v1(98.27,122.68)
  BOTTOM w0.127: v1(98.27,122.68) 97.63,122.05 96.23,122.05 95.6,122.68 90.39,122.68 88.49,124.59 67.91,124.59 65.88,126.62 63.34,126.62 61.69,124.97 61.69,124.49 59.15,121.95 59.15,119 58.52,118.36 SB33.2
NETCN7_25: length 52.6
  TOP w0.127: CN7.25 v1(97,121.41)
  BOTTOM w0.127: SB41.2 58.64,113.84 58.9,114.1 58.9,114.81 59.53,115.44 59.53,121.95 63.82,126.24 65.75,126.24 67.66,124.33 88.11,124.33 90.14,122.3 94.84,122.3 95.73,121.41 v1(97,121.41)
NETCN7_32: length 6.5
  TOP w0.127: R79.2 102.58,116.33 101.31,117.6 CN7.32
NETCN7_33: length 44.5
  TOP w0.102: SB23.2 67.79,113.79
  TOP w0.127: v1(96.72,116.76) 96.29,116.33 CN7.33 ; 67.79,113.79 v1(66.52,115.06)
  BOTTOM w0.127: v1(66.52,115.06) 65.63,115.95 65.63,117.73 66.64,118.75 66.64,121.41 67.79,122.56 86.33,122.56 88.87,120.02 92.93,120.02 96.18,116.76 v1(96.72,116.76)
NETCN7_34: length 46.6
  TOP w0.127: CN7.34 99.13,116.33 98.06,117.4 v1(98.06,117.7) ; SB24.2 65.88,113.54 v1(65.88,114.17)
  BOTTOM w0.127: v1(98.06,117.7) 97.61,117.25 96.08,117.25 93.06,120.27 89.12,120.27 86.58,122.81 67.66,122.81 66.39,121.54 66.39,118.87 65.37,117.86 65.37,115.32 65.88,114.81 v1(65.88,114.17)
NETCN8_2: length 3.5
  TOP w0.127: CN8.2 84.55,117.86 R72.2
NETCN9_2: length 9
  TOP w0.127: CN9.2 115.31,108.86 114.9,108.46 114.9,105.69 112.63,103.42 U10.6
NETCN9_3: length 9.3
  TOP w0.127: CN9.3 115.41,111.63 113.38,109.6 113.38,106.4 113,106.02 U10.10
NETCN9_6: length 10.8
  TOP w0.127: CN9.6 115.69,107.47 115.28,107.06 115.28,105.44 112.62,102.77 U10.5
NETCN9_7: length 11.8
  TOP w0.127: U10.9 113.16,105.37 114.01,106.22 114.01,109.35 115.03,110.36 119.48,110.36 CN9.7
NETCN9_8: length 18.7
  TOP w0.127: CN9.8 121.25,111.35 121.25,109.73 120.62,109.09 118.71,109.09 117.7,110.11 115.41,110.11 114.52,109.22 114.52,105.82 112.77,104.06 111.73,104.06 U10.7
NETCN10_1: length 3.5
  TOP w0.508: CN10.1 85.57,111.12 R92.1
NETCN11_4: length 99.8
  TOP w0.127: 35.56,98.42 32.77,101.22 16.35,101.22 15.84,101.73 v1(15.21,101.73) ; v1(25.47,47.78) 22.09,47.78 17.88,43.56 16.48,43.56 15.08,42.16 12.03,42.16 11.53,41.66 R194.1
  BOTTOM w0.127: v1(15.21,101.73) 15.21,98.17 15.84,97.54 15.84,89.15 18.76,86.23 18.76,76.2 20.57,74.4 20.57,72.14 25.65,67.06 25.65,49.12 26,48.77 26,48.23 25.55,47.78 v1(25.47,47.78)
NETCN11_6: length 83.4
  TOP w0.127: R5.2 28.16,158.62 v1(27.53,158.62) ; 38.1,98.42 34.8,101.73 v1(25.75,101.73)
  BOTTOM w0.127: v1(27.53,158.62) 26.13,157.23 26.13,142.37 24.45,140.69 24.45,133.68 23.36,132.59 23.36,129.79 25.8,127.36 25.8,124.13 25.37,123.7 25.37,111 26.6,109.77 26.6,102.34 25.98,101.73 v1(25.75,101.73)
NETCN11_8: length 43.5
  TOP w0.127: R75.2 15.08,116.71 15.08,103 15.84,102.23 36.83,102.23 40.64,98.42
NETCN11_10: length 124.8
  TOP w0.127: v1(113.25,97.36) 112.62,96.72 111.96,96.72 111.48,97.21 97.5,97.21 92.5,102.21 91.66,102.21 91.36,101.9 85.64,101.9 84.2,103.35 74.31,103.35 72.59,101.63 64.05,101.63 63.19,102.49 62.47,102.49 61.79,101.8 60.5,101.8 60.12,102.18 48.23,102.18 45.69,99.64 44.4,99.64 43.18,98.42 ; v1(117.98,136.25) 118.15,136.25 119.3,135.1 123.13,135.1 R265.2
  BOTTOM w0.127: v1(113.25,97.36) 113.28,97.36 114.42,98.5 114.42,126.54 116.02,128.14 116.02,135.25 117.01,136.25 v1(117.98,136.25)
NETCN11_12: length 125.2
  TOP w0.127: R266.2 124.73,136.73 124.73,135.31 124.23,134.8 119.17,134.8 118.43,135.53 v1(117.98,135.53) ; 45.72,98.42 45.72,98.89 48.76,101.93 60.01,101.93 60.39,101.55 61.89,101.55 62.58,102.23 63.06,102.23 64.13,101.17 72.89,101.17 74.64,102.92 84.02,102.92 85.39,101.55 91.41,101.55 91.74,101.88 92.37,101.88 97.3,96.95 111.37,96.95 112.13,96.19 v1(113.1,96.19)
  BOTTOM w0.127: v1(113.1,96.19) 114.73,97.82 114.73,126.29 118.48,130.05 118.48,135.03 v1(117.98,135.53)
NETCN11_16: length 59
  TOP w0.127: 50.8,98.42 49.24,96.87 49.24,95.63 48.61,95 47.85,95 46.83,93.98 30.45,93.98 28.54,92.08 17.88,92.08 17.49,92.46 15.46,92.46 8.48,85.47 8.48,83.69 8.1,83.31 4.67,83.31 4.16,82.8 4.16,80.66 4.47,80.35 4.47,80.33 CN13.4
NETCN11_18: length 59.5
  TOP w0.127: CN13.6 7.59,82.04 8.99,83.44 8.99,85.34 15.72,92.08 17.37,92.08 17.75,91.69 28.8,91.69 30.83,93.73 46.96,93.73 47.97,94.74 48.99,94.74 49.5,95.25 49.5,96.75 50.21,97.46 52.37,97.46 53.34,98.42 53.34,100.62 R108.1
NETCN11_20: length 127
  TOP w0.127: v1(59.84,8.1) 59.76,8.1 59.28,8.59 59.28,13.84 58.52,14.61 56.23,14.61 52.8,18.03 52.8,30.1 53.94,31.24 53.94,37.85 57.88,41.78 v1(58.39,41.78) ; 55.88,98.42 55.88,100.11 R109.1
  BOTTOM w0.127: v1(58.39,41.78) 58.13,42.04 58.13,44.32 61.54,47.73 61.54,59.26 62.55,60.27 62.55,63.86 61.97,64.44 61.97,65.53 60.52,66.98 60.52,71.86 59.46,72.92 57.96,72.92 57.12,72.09 56.03,72.09 55.57,72.54 55.57,73.76 56.23,74.42 56.23,77.22 56.74,77.72 56.74,84.71 55.09,86.36 55.09,91.82 56.99,93.73 56.99,97.31 55.88,98.42 ; CN23.6 68.91,1.78 62.73,1.78 59.84,4.67 v1(59.84,8.1)
NETCN11_24: length 80.1
  TOP w0.127: v1(19.53,112.78) 19.53,117.35 R76.1 ; v1(15.34,91.06) 15.46,90.93 30.58,90.93 32.61,92.96 47.34,92.96 48.23,93.85 51.15,93.85 51.91,94.61 53.69,94.61 54.07,95 58.9,95 59.66,95.76 59.66,96.9 60.96,98.2 60.96,98.42
  BOTTOM w0.127: v1(19.53,112.78) 19.53,112.01 14.07,106.55 14.07,98.68 15.34,97.41 v1(15.34,91.06)
NETCN11_26: length 78.7
  TOP w0.127: CN13.5 1.87,81.15 1.87,78.87 2.64,78.11 5.94,78.11 10.13,82.3 10.13,85.22 15.08,90.17 30.75,90.17 33.04,92.46 48.48,92.46 49.12,93.09 51.53,93.09 52.29,93.85 54.07,93.85 54.45,94.23 59.4,94.23 59.91,94.74 63.7,94.74 64.48,95.53 64.48,97.44 63.5,98.42
NETCN11_28: length 159.9
  TOP w0.127: U4.10 23.27,151.31 v1(23.59,151.64) 23.27,151.96 U4.11 ; U4.14 v1(20.99,154.43) ; v1(17.24,89.66) 17.37,89.79 26.77,89.79 27.6,88.95 30.5,88.95 33.5,91.95 48.74,91.95 49.37,92.58 51.78,92.58 52.55,93.34 54.45,93.34 54.83,93.73 59.68,93.73 60.19,94.23 64.1,94.23 65.12,95.25 65.12,97.54 66.01,98.42 66.04,98.42 ; U3.14 v1(7.79,154.38) ; U3.11 9.93,151.96 v1(10.26,151.64) 9.93,151.31 U3.10
  BOTTOM w0.127: JP14.3 19.27,83.06 19.27,86.61 17.24,88.65 v1(17.24,89.66) 16.61,90.3 16.61,92.33 16.8,92.52 16.8,101.66 15.59,102.87 15.59,105.47 16.8,106.68 16.8,108.24 20.16,111.6 20.16,111.76 23.34,114.94 23.34,125.73 21.99,127.08 21.99,141.78 24.61,144.4 24.61,150.62 v1(23.59,151.64) 20.99,154.23 v1(20.99,154.43) 19.22,156.21 8.48,156.21 7.84,155.57 7.84,154.43 v1(7.79,154.38) 8.48,153.69 8.48,153.67 10.26,151.89 v1(10.26,151.64)
NETCN11_30: length 186
  TOP w0.127: v1(66.77,58.04) 66.9,58.04 67.46,57.48 70.66,57.48 71.16,57.99 79.52,57.99 81.02,56.49 82.06,56.49 95.68,42.88 95.68,41.33 v1(96.49,40.51) ; R256.1 v1(23.08,10.16)
  BOTTOM w0.127: v1(23.08,10.16) 24.23,9.02 26.38,9.02 29.94,12.57 87.85,12.57 90.14,14.86 90.14,21.34 91.03,22.23 91.03,28.07 90.52,28.57 90.52,31.11 91.28,31.88 91.28,38.61 93.19,40.51 v1(96.49,40.51) ; 68.58,98.42 68.58,97.63 69.82,96.39 69.82,94.87 74.39,90.3 74.39,82.91 74.85,82.45 74.85,76.02 73.6,74.78 73.6,71.27 69.26,66.93 69.26,62.26 66.95,59.94 66.95,58.22 v1(66.77,58.04)
NETCN11_32: length 256
  TOP w0.089: U29.A9 78.23,29.37 77.82,28.96
  TOP w0.127: v1(12.85,11.07) 12.85,11.13 11.82,12.15 U36.4 ; v1(116.02,70.59) 115.97,70.59 115.82,70.43 83.74,70.43 82.39,69.09 73.5,69.09 v1(72.99,69.6) ; U35.4 97.57,14.69 v1(98.39,13.87) ; 77.82,28.96 76.04,27.18 76.04,26.34 73.88,24.18 73.88,17.27 76.68,14.48 v1(76.68,9.91)
  BOTTOM w0.127: v1(116.02,70.59) 114.5,69.06 114.5,60.17 111.98,57.66 111.98,48.77 103.73,40.51 103.73,19.76 98.39,14.43 v1(98.39,13.87) 97.28,12.75 92.63,12.75 90.04,10.16 77.82,10.16 77.57,9.91 v1(76.68,9.91) 75.66,9.91 75.41,10.16 30.7,10.16 27.76,7.21 18.66,7.21 14.09,11.79 13.28,11.79 12.85,11.35 v1(12.85,11.07) ; 71.12,98.42 71.98,97.57 71.98,93.47 74.9,90.55 74.9,83.39 75.28,83.01 75.28,75.82 73.96,74.5 73.96,70.56 v1(72.99,69.6)
NETCN11_34: length 2.5
  TOP w0.508: R111.2 73.66,100.23 73.66,98.42
NETCN11_38: length 2.6
  TOP w0.127: 78.74,98.42 78.74,100.74 R107.2
NETCN12_2: length 27.7
  TOP w0.127: v1(114.55,87.38) 115.06,87.88 115.97,87.88 116.44,87.41 U17.1 116.44,85.84 117.01,85.27 121.08,85.27 121.76,84.58 121.76,82.39 CN15.7 120.4,81.03 R153.1 ; RS1.14 109.74,88.12 v1(109.52,88.34) 109.29,88.34 108.45,87.5 CN12.2
  BOTTOM w0.127: v1(114.55,87.38) 113.63,86.46 112.59,86.46 111.02,88.04 109.82,88.04 v1(109.52,88.34)
NETCN12_4: length 24.4
  TOP w0.127: RS1.12 110.7,87.63 110.67,87.66 v1(109.57,87.66) 109.06,87.15 109.06,86.74 108.55,86.23 CN12.4 ; v1(114.5,85.5) 114.75,85.5 115.14,85.89 U17.3 ; v1(115.79,78.49) 115.79,78.61 R155.2 120.14,79.25 CN15.9
  BOTTOM w0.127: v1(109.57,87.66) 110.97,87.66 112.44,86.18 113.81,86.18 v1(114.5,85.5) 114.5,84.79 116.17,83.11 116.17,78.87 v1(115.79,78.49)
NETCN12_6: length 30
  TOP w0.127: v1(114.01,75.18) 115.67,75.18 R160.1 R162.2 119.89,72.9 CN15.13 ; RS1.10 109.93,87.12 v1(109.53,86.72) 109.14,86.32 109.14,86.23 109.11,86.21 109.11,85.47 108.6,84.96 CN12.6 ; v1(114.14,83.69) 114.9,83.69 115.14,83.93 U17.4
  BOTTOM w0.127: v1(114.01,75.18) 114.7,75.87 114.7,83.13 v1(114.14,83.69) 113.68,83.69 110.66,86.72 v1(109.53,86.72)
NETCN12_8: length 20.2
  TOP w0.127: CN12.8 108.55,83.69 v1(109.25,84.39) 109.37,84.51 109.37,86.08 109.54,86.26 109.82,86.26 110.18,86.62 RS1.8 ; CN15.5 120.03,84.44 U17.5 116.44,82.82 R152.1 115.67,82.04 114.27,82.04 v1(114.01,81.79)
  BOTTOM w0.127: v1(109.25,84.39) 111.86,81.79 v1(114.01,81.79)
NETCN12_10: length 29.1
  TOP w0.127: CN12.10 v1(109.44,82.42) 110.08,82.42 110.57,82.92 U18.3 110.57,83.86 109.95,84.48 109.95,85.19 110.38,85.62 RS1.4 ; v1(111.14,71.4) 111.42,71.12 CN15.15
  BOTTOM w0.127: v1(111.14,71.4) 112.24,72.49 112.24,79.63 v1(109.44,82.42)
